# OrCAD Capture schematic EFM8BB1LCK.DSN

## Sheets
1 PAGE1: size B; title: EFM8BB1LCK; rev: 1.0; note: EFM8BB1ULCK
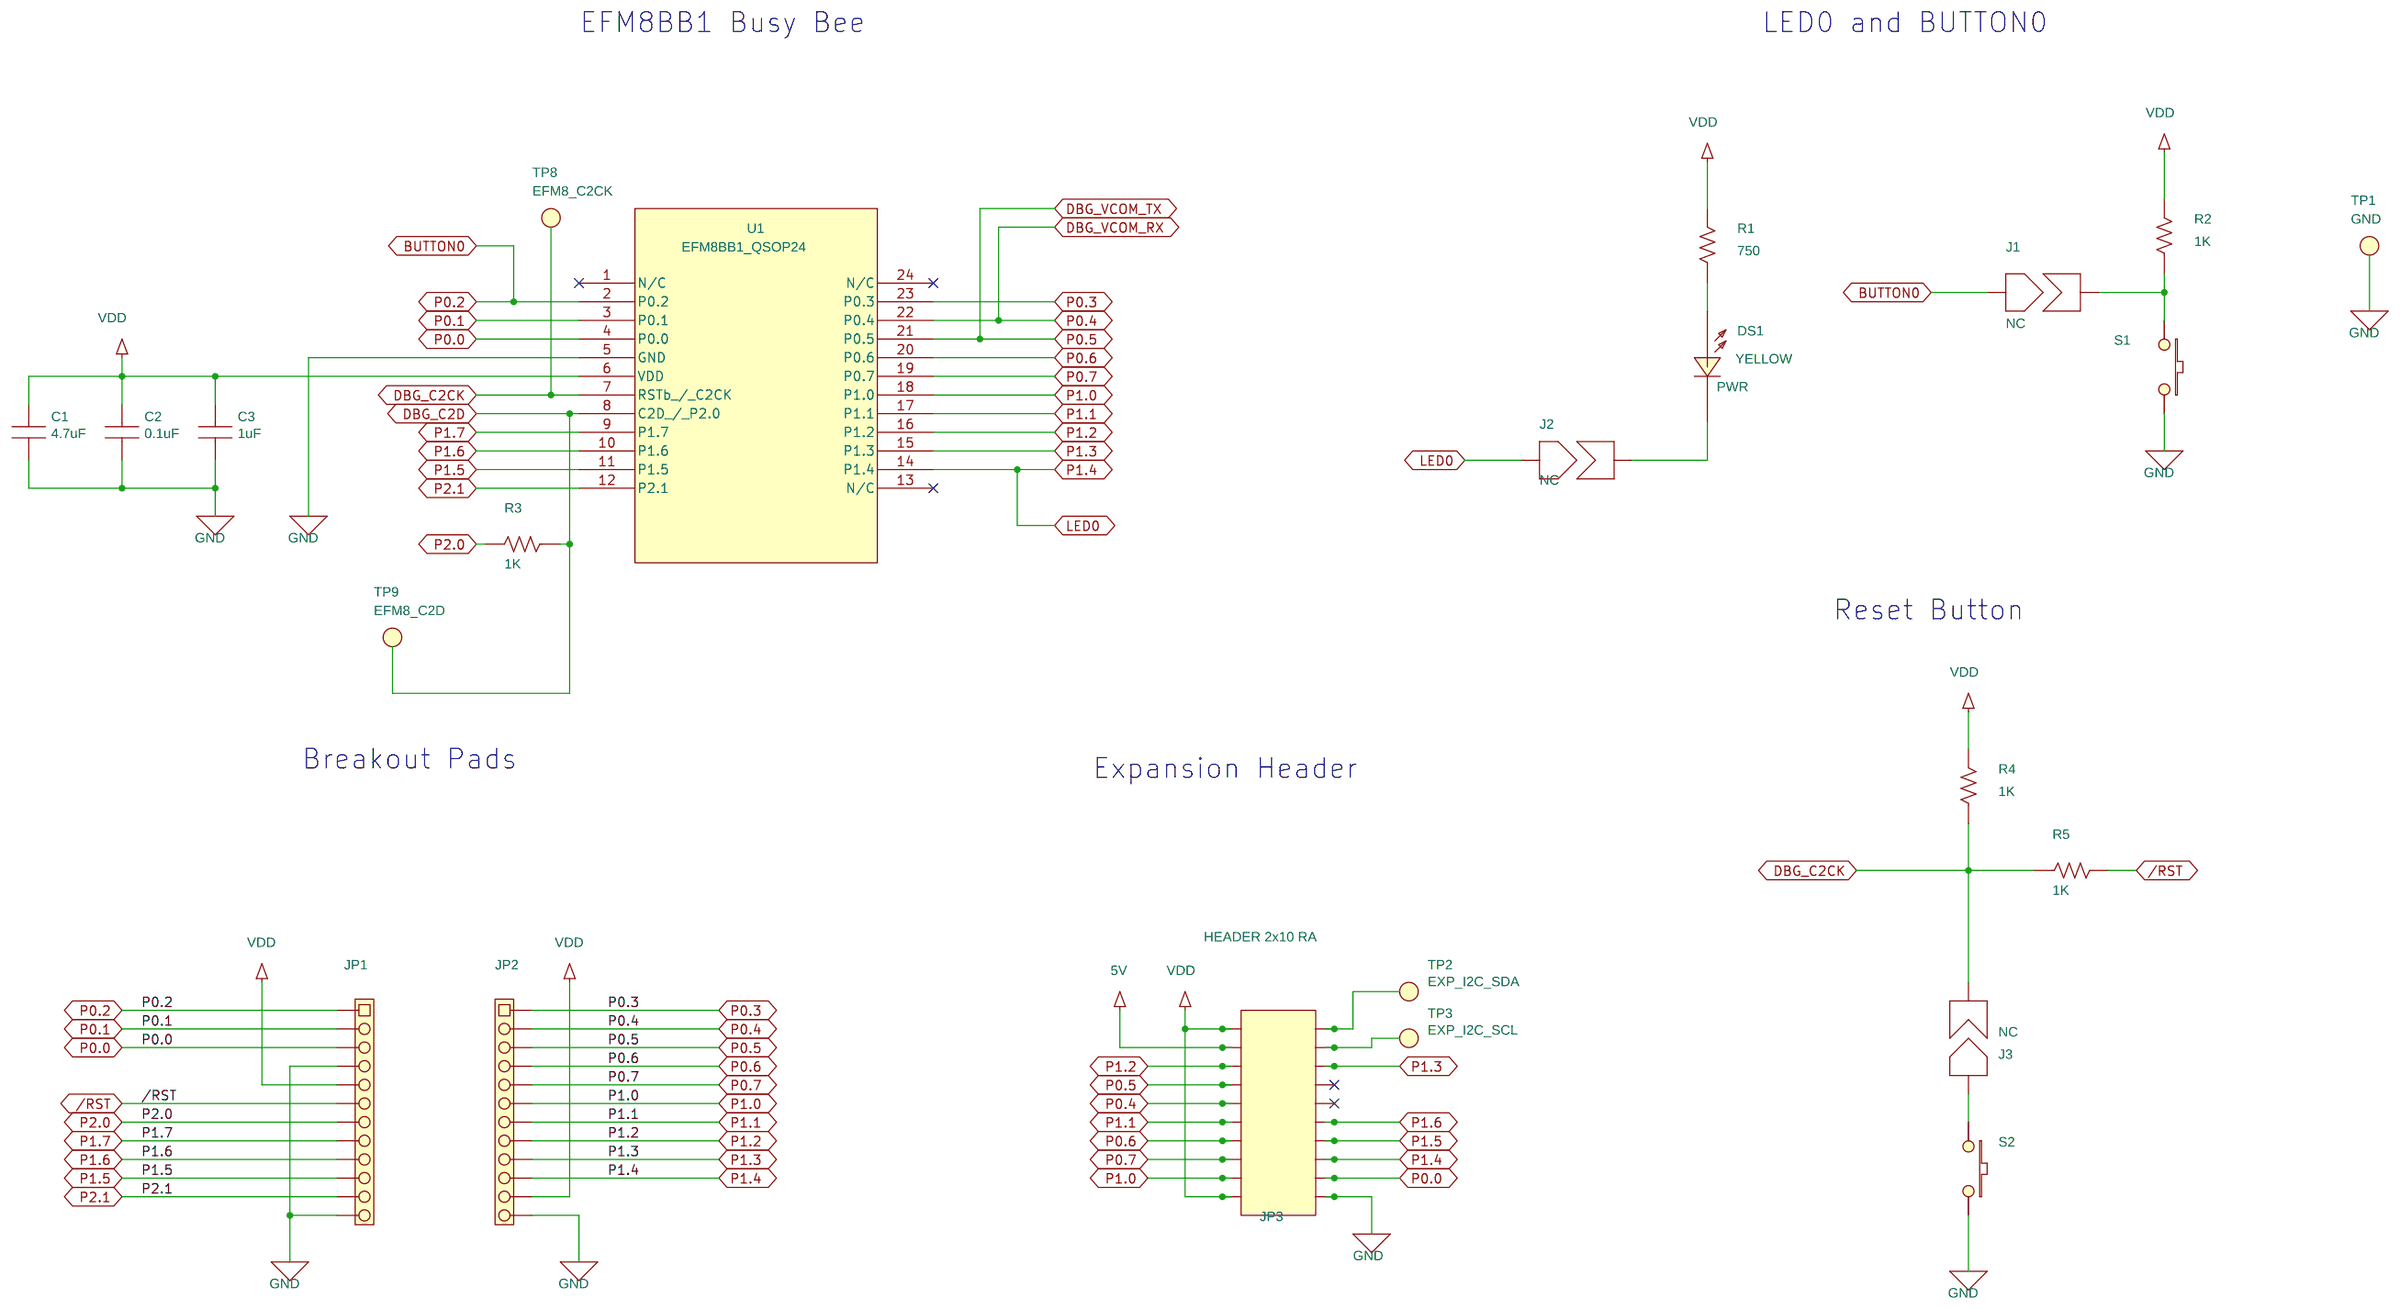
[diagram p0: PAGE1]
2 PAGE2: size B
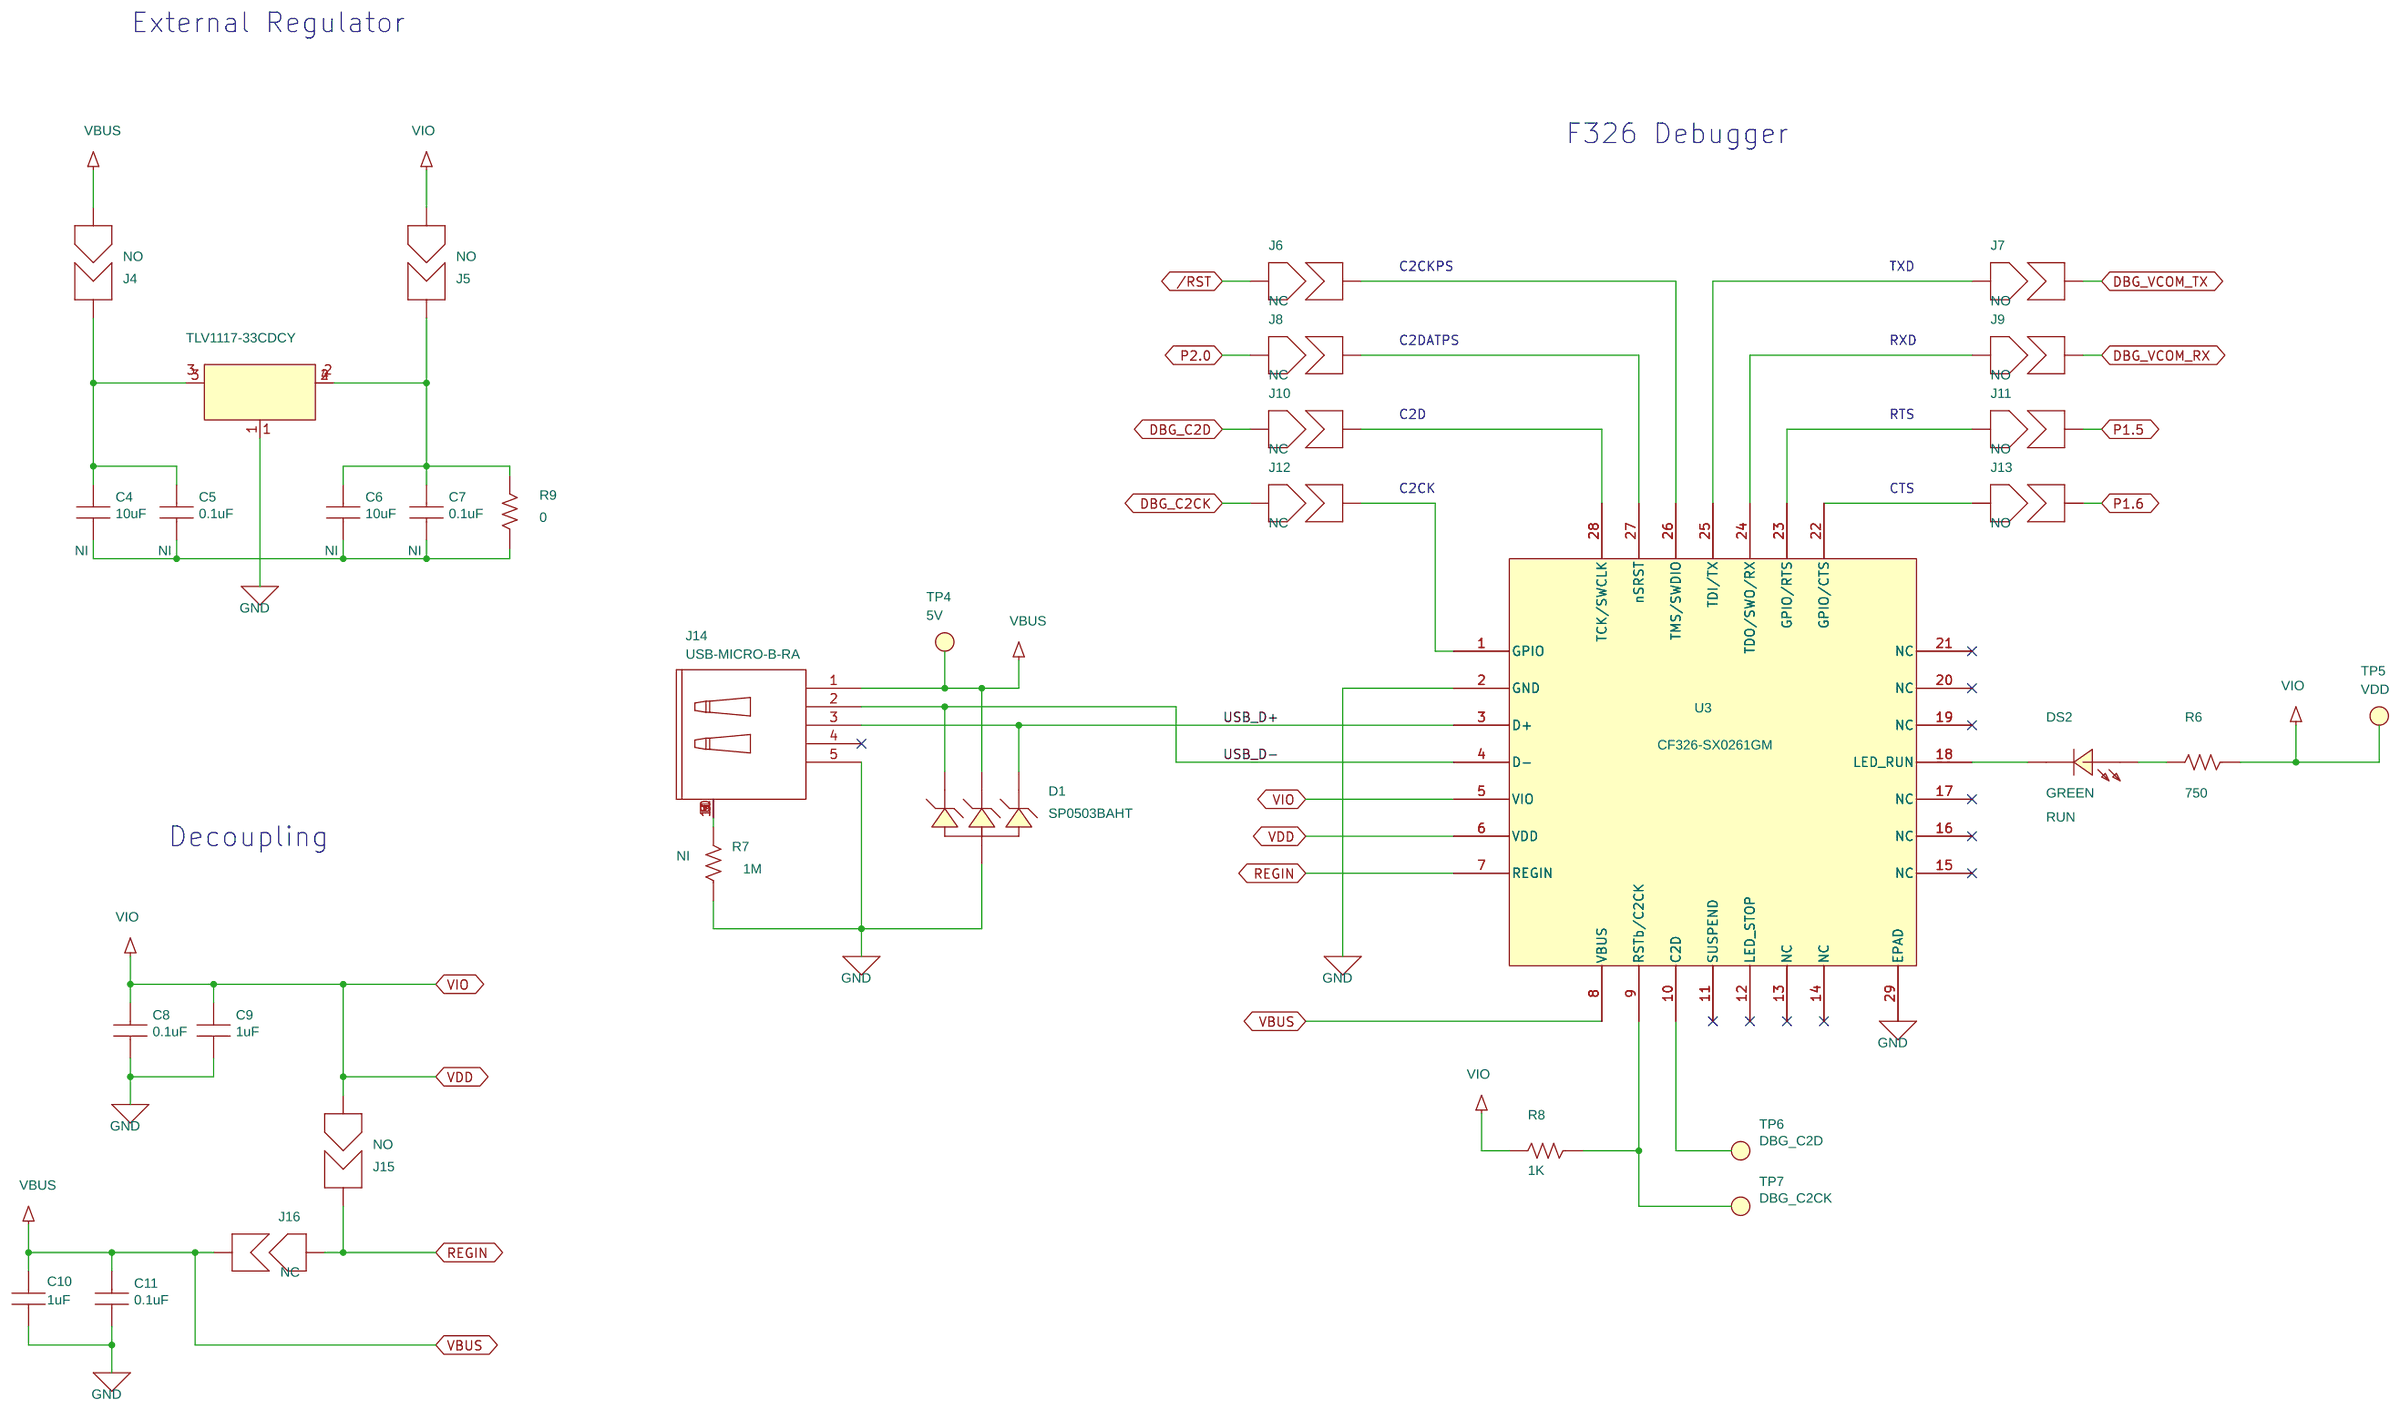
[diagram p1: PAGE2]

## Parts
sheet PAGE1
C1  4.7uF  [C0603]
C2  0.1uF  [C0603]
C3  1uF  [C0603]
DS1  YELLOW  [LED0603-KA]
J1  NC  [SB0402-NC]
J2  NC  [SB0402-NC]
J3  NC  [SB0402-NC]
JP1  HEADER 1x12  [CONN1X12]
JP2  HEADER 1x12  [CONN1X12]
JP3  HEADER 2x10 RA  [CONN2X10-MRA]
R1  750  [R0402]
R2  1K  [R0402]
R3  1K  [R0402]
R4  1K  [R0402]
R5  1K  [R0402]
S1  MOMENTARY  [SW4N6.5X4.5-PB]
S2  MOMENTARY  [SW4N6.5X4.5-PB]
TP1  BLUE  [TESTPOINT]
TP2  WHITE  [TESTPOINT]
TP3  WHITE  [TESTPOINT]
TP8  BLUE  [TESTPOINT]
TP9  BLUE  [TESTPOINT]
U1  EFM8BB1_QSOP24  [SOP24N6.0P0.635]
sheet PAGE2
C4  10uF  [C0603]
C5  0.1uF  [C0603]
C6  10uF  [C0603]
C7  0.1uF  [C0603]
C8  0.1uF  [C0603]
C9  1uF  [C0603]
C10  1uF  [C0603]
C11  0.1uF  [C0603]
D1  SP0503BAHT  [SOT143-AKKK]
DS2  GREEN  [LED0603-KA]
J4  NO  [SB0402-NO]
J5  NO  [SB0402-NO]
J6  NC  [SB0402-NC]
J7  NO  [SB0402-NO]
J8  NC  [SB0402-NC]
J9  NO  [SB0402-NO]
J10  NC  [SB0402-NC]
J11  NO  [SB0402-NO]
J12  NC  [SB0402-NC]
J13  NO  [SB0402-NO]
J14  USB-MICRO-B-RA  [MICRO-USB-B-RA-SMT]
J15  NO  [SB0402-NO]
J16  NC  [SB0402-NC]
R6  750  [R0402]
R7  1M  [R0603]
R8  1K  [R0402]
R9  0  [R0603]
TP4  BLUE  [TESTPOINT]
TP5  BLUE  [TESTPOINT]
TP6  WHITE  [TESTPOINT]
TP7  WHITE  [TESTPOINT]
U2  TLV1117-33CDCY  [SOT223]
U3  CF326-SX0261GM  [QFN28N5X5P0.5]

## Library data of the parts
C1 = CAP_NP: CAP, 4.7uF, 10V, ±10%, X5R, 0603; Manufacturer: Venkel; ManufacturerPN: C0603X5R100-475K; SiLabsPN: C0603X5R100-475K; Tolerance: ±10%; Type: X5R; Voltage: 10V; Datasheet: PID_C.pdf
C2 C8 C11 = CAP_NP: CAP, 0.1uF, 10V, ±10%, X7R, 0603; Manufacturer: Venkel; ManufacturerPN: C0603X7R100-104K; SiLabsPN: C0603X7R100-104K; Tolerance: ±10%; Type: X7R; Voltage: 10V; Datasheet: PID_C.pdf
C3 C9 C10 = CAP_NP: CAP, 1uF, 10V, ±10%, X7R, 0603; Manufacturer: Venkel; ManufacturerPN: C0603X7R100-105K; SiLabsPN: C0603X7R100-105K; Tolerance: ±10%; Type: X7R; Voltage: 10V; Datasheet: PID_C.pdf
DS1 = LED: LED, YELLOW, 589nM, 20mA, 2V, 104mcd, 0603; Manufacturer: LITE-ON TECHNOLOGY CORP; ManufacturerPN: LTST-C190KSKT; SiLabsPN: LTST-C190KSKT; Silk: PWR; Datasheet: P_100_LTST-C190KSKT.pdf
J1-J3 J6 J8 J10 J12 J16 = SolderBump: SOLDER BUMP JUMPER, NC, 0402; FPLIST: SB0402-NC,SB0402-NC-10; Manufacturer: N/A; ManufacturerPN: N/A; Type: PCB Feature
JP1 JP2 = HEADER_12: Header, 1x12, 0.1in pitch, Tin Plated; Installed Component: NI; Manufacturer: Samtec; ManufacturerPN: TSW-112-07-T-S; SiLabsPN: TSW-112-07-T-S; Type: Header; Datasheet: TSW_TH.PDF
JP3 = 2x10_Header: Header, 2x10, Right Angle, 0.1in pitch, 30u Au Plated; Installed Component: NI; Manufacturer: Samtec; ManufacturerPN: TSW-110-25-G-D-RA; SiLabsPN: TSW-110-25-G-D-RA; Type: Header; Datasheet: TSW_TH.PDF
R1 R6 = RES: RES, 750, 1/10W, ±1%, ThickFilm, 0402; FPLIST: R0402,R0402L; Manufacturer: Venkel; ManufacturerPN: CR0402-10W-7500FT; Rating: 1/10W; SiLabsPN: TMP-8618; Tolerance: ±1%; Type: ThickFilm; Datasheet: PID_CR.pdf
R2-R5 R8 = RES: RES, 1K, 1/10W, ±1%, ThickFilm, 0402; FPLIST: R0402,R0402L; Manufacturer: Venkel; ManufacturerPN: CR0402-10W-1001FT; Rating: 1/10W; SiLabsPN: TMP-8617; Tolerance: ±1%; Type: ThickFilm; Datasheet: PID_CR.pdf
S1 S2 = SW_PUSHBUTTON_SHORT: SWITCH, PB, NO, MOMENTARY, TACTILE, LIGHT TOUCH 130GF, 6MM, PTH; Manufacturer: PANASONIC CORP; ManufacturerPN: EVQ-PAD04M; Part_Type: SWITCH; SiLabsPN: EVQ-PAD04M; Silk: P1.7; Type: Tactile; Datasheet: ATK0000CE10.pdf
TP1 = TEST_POINT: TESTPOINT, BLUE, PTH; Installed Component: NI; Manufacturer: Kobiconn; ManufacturerPN: 151-205-RC; SiLabsPN: 151-205; Silk: GND; Type: Loop; Datasheet: KC-300780.pdf
TP2 = TEST_POINT: TESTPOINT, WHITE, PTH; Installed Component: NI; Manufacturer: Kobiconn; ManufacturerPN: 151-201-RC; SiLabsPN: 151-201; Silk: EXP_I2C_SDA; Type: Loop; Datasheet: KC-300780.pdf
TP3 = TEST_POINT: TESTPOINT, WHITE, PTH; Installed Component: NI; Manufacturer: Kobiconn; ManufacturerPN: 151-201-RC; SiLabsPN: 151-201; Silk: EXP_I2C_SCL; Type: Loop; Datasheet: KC-300780.pdf
TP8 = TEST_POINT: TESTPOINT, BLUE, PTH; Installed Component: NI; Manufacturer: Kobiconn; ManufacturerPN: 151-205-RC; SiLabsPN: 151-205; Silk: EFM8_C2CK; Type: Loop; Datasheet: KC-300780.pdf
TP9 = TEST_POINT: TESTPOINT, BLUE, PTH; Installed Component: NI; Manufacturer: Kobiconn; ManufacturerPN: 151-205-RC; SiLabsPN: 151-205; Silk: EFM8_C2D; Type: Loop; Datasheet: KC-300780.pdf
U1 = EFM8BB1_QSOP24: IC, MCU, 25MHz, 8K Flash, QSOP24; Manufacturer: SiLabs; ManufacturerPN: EFM8BB10F8G-A-QSOP24; SiLabsPN: TMP-8647; Type: MCU; Datasheet: EFM8BB1_DataSheet.pdf
C4 C6 = CAP_NP: CAP, 10uF, 10V, ±10%, X5R, 0603; FPLIST: C0603,C0603L; Installed Component: NI; Manufacturer: Venkel; ManufacturerPN: C0603X5R100-106K; SiLabsPN: C0603X5R100-106K; Tolerance: ±10%; Type: X5R; Voltage: 10V; Datasheet: PID_C.pdf
C5 C7 = CAP_NP: CAP, 0.1uF, 10V, ±10%, X7R, 0603; Installed Component: NI; Manufacturer: Venkel; ManufacturerPN: C0603X7R100-104K; SiLabsPN: C0603X7R100-104K; Tolerance: ±10%; Type: X7R; Voltage: 10V; Datasheet: PID_C.pdf
D1 = ZENER_TRIPLE_COM_ANODE: Diode Array, TVS Avalanche; FPLIST: SOT143-AKKK,SOT143; Manufacturer: Littlefuse; ManufacturerPN: SP0503BAHTG; Rating: 300mW; SiLabsPN: SP0503BAHTG; Type: TVS; Voltage: 20V; Datasheet: SP05xxBA.pdf
DS2 = LED: LED, GREEN, 571nM, 20mA, 2V, 35mcd, 0603; Manufacturer: LITE-ON TECHNOLOGY CORP; ManufacturerPN: LTST-C190KGKT; SiLabsPN: LTST-C190KGKT; Silk: RUN; Datasheet: P_100_LTST-C190KGKT.pdf
J4 J5 J7 J9 J11 J13 J15 = SolderBump: SOLDER BUMP JUMPER, NO, 0402; FPLIST: SB0402-NO,SB0402-NO-10; Manufacturer: N/A; ManufacturerPN: N/A; Type: PCB Feature
J14 = CN-5USB-OTG_6SH: CONN, RECEPT MICRO B, USB2.0 5POS, RA; Manufacturer: HIROSE; ManufacturerPN: ZX62-B-5P; SiLabsPN: ZX62-B-5P; Type: USB; Datasheet: e24200011.pdf
R7 = RES: RES, 1M, 1/16W, ±1%, ThickFilm, 0603; Installed Component: NI; Manufacturer: Venkel; ManufacturerPN: CR0603-16W-1004F; Rating: 1/16W; SiLabsPN: CR0603-16W-1004F; Tolerance: ±1%; Type: ThickFilm; Datasheet: PID_CR.pdf
R9 = RES: RES, 0 Ohm, 1A, ThickFilm, 0603; FPLIST: R0603,R0603L; Installed Component: NI; Manufacturer: Panasonic; ManufacturerPN: ERJ-3GEY0R00V; Rating: 1A; SiLabsPN: ERJ-3GEY0R00V; Type: ThickFilm; Datasheet: AOA0000CE1.pdf
TP4 = TEST_POINT: TESTPOINT, BLUE, PTH; Installed Component: NI; Manufacturer: Kobiconn; ManufacturerPN: 151-205-RC; SiLabsPN: 151-205; Silk: 5V; Type: Loop; Datasheet: KC-300780.pdf
TP5 = TEST_POINT: TESTPOINT, BLUE, PTH; Installed Component: NI; Manufacturer: Kobiconn; ManufacturerPN: 151-205-RC; SiLabsPN: 151-205; Silk: VDD; Type: Loop; Datasheet: KC-300780.pdf
TP6 = TEST_POINT: TESTPOINT, WHITE, PTH; Installed Component: NI; Manufacturer: Kobiconn; ManufacturerPN: 151-201-RC; SiLabsPN: 151-201; Silk: DBG_C2D; Type: Loop; Datasheet: KC-300780.pdf
TP7 = TEST_POINT: TESTPOINT, WHITE, PTH; Installed Component: NI; Manufacturer: Kobiconn; ManufacturerPN: 151-201-RC; SiLabsPN: 151-201; Silk: DBG_C2CK; Type: Loop; Datasheet: KC-300780.pdf
U2 = REG_3-TERM_4P-GOIO: IC, VOLTAGE REGULATOR, LDO, 3.3V, SOT223; Installed Component: NI; Manufacturer: TI; Type: LDO; Voltage: 3.3V; Datasheet: TLV1117.pdf
U3 = CF326: IC, MCU, ToolStick DEBUG Adp., Full Speed USB, 16 KB Flash MCU, QFN28; Manufacturer: SiLabs; Type: MCU; Datasheet: C8051F326.pdf

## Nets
5V: C10.2 C11.1 D1.K2(CATHODE) J4.1(IO1) J14.1(+V) J16.2(IO2) JP3.3 TP4.1(Point) U3.8(VBUS)
GND: C1.2 C2.2 C3.2 C8.2 C9.2 C10.1 C11.2 D1.A(ANODE) J14.5(GND) JP1.4 JP1.12 JP2.12 JP3.20 R7.1 S1.1 S1.2 S2.3 S2.4 TP1.1(Point) U1.5(GND) U2.1(GND) U3.2(GND) U3.29(EPAD)
VDD: C1.1 C2.1 C3.1 C8.1 C9.1 J5.1(IO1) J15.1(IO1) JP1.5 JP2.11 JP3.1 JP3.19 R1.2 R2.2 R4.2 R6.1 R8.2 TP5.1(Point) U1.6(VDD) U3.5(VIO) U3.6(VDD)
/RST: J6.1(IO1) JP1.6 R5.2
BUTTON0: J1.1(IO1) JP1.1 U1.2(P0.2)
DBG_C2CK: J3.2(IO2) J12.1(IO1) R4.1 R5.1 TP8.1(Point) U1.7(RSTb_/_C2CK)
DBG_C2D: J10.1(IO1) R3.1 TP9.1(Point) U1.8(C2D_/_P2.0)
DBG_VCOM_RX: J9.2(IO2) JP2.2 JP3.9 U1.22(P0.4)
DBG_VCOM_TX: J7.2(IO2) JP2.3 JP3.7 U1.21(P0.5)
LED0: J2.1(IO1) JP2.10 JP3.16 U1.14(P1.4)
P0.0: JP1.3 JP3.18 U1.4(P0.0)
P0.1: JP1.2 U1.3(P0.1)
P0.3: JP2.1 U1.23(P0.3)
P0.6: JP2.4 JP3.13 U1.20(P0.6)
P0.7: JP2.5 JP3.15 U1.19(P0.7)
P1.0: JP2.6 JP3.17 U1.18(P1.0)
P1.1: JP2.7 JP3.11 U1.17(P1.1)
P1.2: JP2.8 JP3.5 U1.16(P1.2)
P1.3: JP2.9 JP3.6 U1.15(P1.3)
P1.5: J11.2(IO2) JP1.10 JP3.14 U1.11(P1.5)
P1.6: J13.2(IO2) JP1.9 JP3.12 U1.10(P1.6)
P1.7: JP1.8 U1.9(P1.7)
P2.0: J8.1(IO1) JP1.7 R3.2
P2.1: JP1.11 U1.12(P2.1)
REGIN: J15.2(IO2) J16.1(IO1) U3.7(REGIN)
USB_D+: D1.K1(CATHODE) J14.3(D+) U3.3(D+)
USB_D-: D1.K3(CATHODE) J14.2(D-) U3.4(D-)
N16777595: DS1.K(CATHODE) J2.2(IO2)
N16777613: DS1.A(ANODE) R1.1
N16777619: J1.2(IO2) R2.1 S1.3 S1.4
N16777914: J3.1(IO1) S2.1 S2.2
N16779324: DS2.K(CATHODE) U3.18(LED_RUN)
N16779354: J8.2(IO2) U3.27(nSRST)
N16779358: J6.2(IO2) U3.26(TMS/SWDIO)
N16779370: J11.1(IO1) U3.23(GPIO/RTS)
N16779388: J13.1(IO1) U3.22(GPIO/CTS)
N16779536: J14.6(SH) J14.7(SH) J14.8(SH) J14.9(SH) J14.10(SH) J14.11(SH) R7.2
N16779561: J12.2(IO2) U3.1(GPIO)
N16779616: J10.2(IO2) U3.28(TCK/SWCLK)
N16779711: J9.1(IO1) U3.24(TDO/SWO/RX)
N16779715: J7.1(IO1) U3.25(TDI/TX)
N16779762: R8.1 TP7.1(Point) U3.9(RSTb/C2CK)
N16779784: TP6.1(Point) U3.10(C2D)
N16785491: C4.1 C5.1 J4.2(IO2) U2.3(IN)
N16785510: C6.1 C7.1 J5.2(IO2) R9.2 U2.2(OUT) U2.4(OUT)
N16785552: C4.2 C5.2 C6.2 C7.2 R9.1
N16791450: JP3.4 TP3.1(Point)
N16791459: JP3.2 TP2.1(Point)
N16792148: DS2.A(ANODE) R6.2

Not connected (* = marked no-connect by the designer): J14 4(ID)*; JP3 8* 10*; U1 1(N/C)* 13(N/C)* 24(N/C)*; U3 11(SUSPEND)* 12(LED_STOP)* 13(NC)* 14(NC)* 15(NC)* 16(NC)* 17(NC)* 19(NC)* 20(NC)* 21(NC)*

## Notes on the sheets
sheet 1
- EFM8BB1 Busy Bee
- LED0 and BUTTON0
- Reset Button
- Breakout Pads
- Expansion Header
sheet 2
- External Regulator
- F326 Debugger
- C2CKPS
- TXD
- C2DATPS
- RXD
- C2D
- RTS
- C2CK
- CTS
- Decoupling
